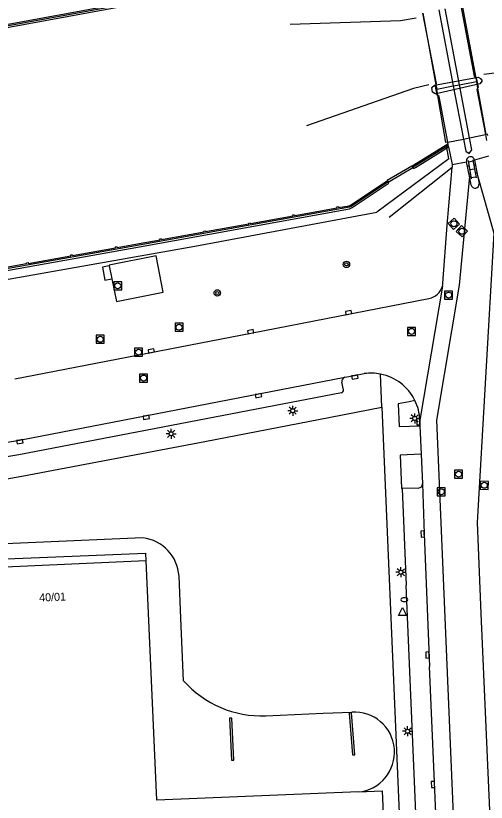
# Model space of a CAD drawing. Extents: x 132999 to 136000, y 398499 to 400501.
# Drawn here: x 133423.1 to 133482, y 398750.4 to 398848.7 of the extents above; entities that cross this region are included whole.
import ezdxf

# ---------------------------------------------------------------- set-up
doc = ezdxf.new("R2010")
doc.units = 0
for name, color, linetype in [('gg-afsc-hekwerk', 7, 'Continuous'), ('gg-afsc-muur', 7, 'Continuous'), ('gg-anno-huisnummerreeks BGT', 7, 'Continuous'), ('gg-bbg-hoofdgebouw', 7, 'Continuous'), ('gg-bbg-luifel en loopbrug', 7, 'Continuous'), ('gg-bbg-onder overbouw', 7, 'Continuous'), ('gg-bbg-pand overbouw', 7, 'Continuous'), ('gg-knt-BGT kruinlijn', 7, 'Continuous'), ('gg-knt-verharding', 7, 'Continuous'), ('gg-knt-verharding niveau 01', 7, 'Continuous'), ('gg-knt-verharding nz', 7, 'Continuous'), ('gg-kwrk-betonelement', 7, 'Continuous'), ('gg-kwrk-geleidewerk', 7, 'Continuous'), ('gt-grn-weggrens', 7, 'Continuous'), ('gt-symb-boom', 7, 'Continuous'), ('gt-symb-brandkraan', 7, 'Continuous'), ('gt-symb-klinker verharding', 7, 'Continuous'), ('gt-symb-kolk', 7, 'Continuous'), ('gt-symb-lichtmast', 7, 'Continuous'), ('gt-symb-rioolschacht', 7, 'Continuous'), ('gt-symb-waterafsluiter', 7, 'Continuous'), ('gx-grn-maaiveld', 7, 'Continuous')]:
    doc.layers.add(name, color=color, linetype=linetype)

# ---------------------------------------------------------------- blocks, each defined once
blk = doc.blocks.new('gt0-RS')
at = {"layer": 'gt-symb-rioolschacht'}
blk.add_lwpolyline([(-0.5, -0.5), (0.5, -0.5), (0.5, 0.5), (-0.5, 0.5)], close=True, dxfattribs=at)
blk.add_circle((0, 0), 0.375, dxfattribs=at)
blk = doc.blocks.new('gt0-KL1')
at = {"layer": 'gt-symb-klinker verharding'}
for p, q in [((-1.15, 0.3), (1.15, 0.3)), ((-1, -0.3), (-1, 0.3)), ((-0.5, 0.3), (-0.5, 0.45)), ((0, -0.3), (0, 0.3)), ((0.5, 0.3), (0.5, 0.45)), ((1, -0.3), (1, 0.3)), ((-1.15, -0.3), (1.15, -0.3)), ((-0.5, -0.45), (-0.5, -0.3)), ((0.5, -0.45), (0.5, -0.3))]:
    blk.add_line(p, q, dxfattribs=at)
blk = doc.blocks.new('gt0-KOLK')
at = {"layer": 'gt-symb-kolk'}
blk.add_lwpolyline([(0, 0), (0.375, 0), (0.375, 0.4), (-0.375, 0.4), (-0.375, 0), (0, 0)], dxfattribs=at)
blk = doc.blocks.new('gt0-BOOM')
at = {"layer": 'gt-symb-boom'}
for radius in [0.4, 0.2]:
    blk.add_circle((0, 0), radius, dxfattribs=at)
blk = doc.blocks.new('gt0-LMAST')
at = {"layer": 'gt-symb-lichtmast'}
for p, q in [((-0.182, 0.173), (-0.447, 0.438)), ((-0.005, 0.246), (-0.005, 0.621)), ((0.172, 0.173), (0.437, 0.438)), ((-0.255, -0.004), (-0.63, -0.004)), ((-0.182, -0.181), (-0.447, -0.446)), ((-0.005, -0.254), (-0.005, -0.629)), ((0.437, -0.446), (0.172, -0.181)), ((0.245, -0.004), (0.62, -0.004))]:
    blk.add_line(p, q, dxfattribs=at)
blk.add_circle((-0.005, -0.004), 0.25, dxfattribs=at)
blk = doc.blocks.new('gt0-WAFSL')
at = {"layer": 'gt-symb-waterafsluiter'}
for p, q in [((-0.5, -0.333), (0, 0.667)), ((0, 0.667), (0.5, -0.333)), ((0.5, -0.333), (-0.5, -0.333))]:
    blk.add_line(p, q, dxfattribs=at)
blk = doc.blocks.new('gt0-BR')
at = {"layer": 'gt-symb-brandkraan'}
for centre, radius, start, end in [((-0.244, 0), 0.206, 107.56694, 252.43307), ((0.599, -2.664), 3, 106.89205, 107.56694), ((0, -0.691), 0.938, 73.10799, 106.89205), ((-0.599, -2.664), 3, 72.43309, 73.10799), ((0.244, 0), 0.206, 287.56695, 72.43309), ((0.599, 2.664), 3, 252.43307, 253.10797), ((0, 0.691), 0.938, 253.10797, 286.89206), ((-0.599, 2.664), 3, 286.89206, 287.56695)]:
    blk.add_arc(centre, radius, start, end, dxfattribs=at)

msp = doc.modelspace()

# ---------------------------------------------------------------- linework, layer by layer
at = {"layer": 'gg-afsc-hekwerk'}
for p, q in [((133476.018, 398849.386), (133477.829, 398839.889)), ((133478.62, 398840.037), (133476.823, 398849.542)), ((133477.829, 398839.889), (133479.095, 398833.253)), ((133479.873, 398833.409), (133478.62, 398840.037)), ((133481.849, 398833.804), (133481.988, 398833.081)), ((133477.253, 398832.286), (133477.142, 398832.862)), ((133469.828, 398823.495), (133477.677, 398829.729)), ((133468.883, 398799.753), (133474.043, 398679.467))]:
    msp.add_line(p, q, dxfattribs=at)
for points in [[(133478.767, 398849.918), (133480.439, 398841.096), (133480.639, 398840.861)], [(133475.665, 398840.028), (133475.725, 398840.213), (133474.043, 398849.004)], [(133480.639, 398840.861), (133480.734, 398840.749), (133480.925, 398839.682), (133480.871, 398839.593)], [(133475.902, 398838.682), (133475.815, 398838.754), (133475.613, 398839.87), (133475.665, 398840.028)], [(133480.871, 398839.593), (133480.777, 398839.437), (133481.849, 398833.804)], [(133477.142, 398832.862), (133476.046, 398838.563), (133475.902, 398838.682)], [(133479.095, 398833.253), (133479.381, 398831.751), (133479.821, 398831.465), (133480.156, 398831.914), (133479.873, 398833.409)], [(133415.609, 398789.703), (133415.609, 398789.722), (133417.98, 398790.069), (133423.912, 398791.103), (133446.77, 398795.458), (133462.485, 398798.488), (133468.883, 398799.753)]]:
    msp.add_lwpolyline(points, dxfattribs=at)
at = {"layer": 'gg-afsc-muur'}
for points in [[(133472.587, 398856.696), (133472.231, 398856.63), (133456.851, 398853.792), (133440.667, 398850.81), (133421.336, 398847.253), (133415.37, 398846.154), (133409.432, 398845.103), (133403.529, 398844.097), (133397.579, 398843.125), (133391.652, 398842.19), (133385.708, 398841.335), (133379.726, 398840.569), (133373.787, 398839.803), (133367.81, 398839.049), (133361.852, 398838.439), (133355.825, 398837.84), (133349.854, 398837.251), (133343.856, 398836.777), (133337.878, 398836.337)], [(133477.129, 398832.399), (133473.007, 398829.849), (133472.837, 398829.744)], [(133469.643, 398827.875), (133469.585, 398827.836), (133465.078, 398824.837), (133464.842, 398824.728)], [(133464.842, 398824.728), (133438.592, 398819.995), (133415.21, 398815.818), (133393.006, 398811.801), (133369.98, 398807.654), (133351.29, 398804.346)], [(133450.387, 398755.638), (133450.164, 398760.867), (133449.872, 398760.858), (133450.095, 398755.63), (133450.387, 398755.638)], [(133465.113, 398761.532), (133464.828, 398761.51), (133465.225, 398756.292), (133465.51, 398756.314), (133465.113, 398761.532)]]:
    msp.add_lwpolyline(points, dxfattribs=at)
at = {"layer": 'gg-bbg-hoofdgebouw'}
for points in [[(133465.972, 398751.653), (133440.764, 398750.615), (133439.456, 398780.533), (133439.39, 398780.53)], [(133465.972, 398751.653), (133468.944, 398751.775), (133472.201, 398676.846)]]:
    msp.add_lwpolyline(points, dxfattribs=at)
at = {"layer": 'gg-bbg-luifel en loopbrug'}
msp.add_line((133439.039, 398783.401), (133415.805, 398782.401), dxfattribs=at)
for points in [[(133444.131, 398765.558), (133443.786, 398773.361), (133443.555, 398778.625)], [(133454.395, 398761.168), (133461.581, 398761.48), (133465.131, 398761.631)]]:
    msp.add_lwpolyline(points, dxfattribs=at)
for centre, radius, start, end in [((133438.449, 398778.32), 5.115, 3.41746, 83.37698), ((133453.852, 398774.093), 12.936, 221.28112, 272.40526), ((133465.479, 398756.636), 5.007, 275.64532, 93.9903)]:
    msp.add_arc(centre, radius, start, end, dxfattribs=at)
at = {"layer": 'gg-bbg-onder overbouw'}
msp.add_line((133439.39, 398780.53), (133415.901, 398779.498), dxfattribs=at)
at = {"layer": 'gg-bbg-pand overbouw'}
msp.add_lwpolyline([(133415.867, 398780.523), (133439.348, 398781.513), (133439.39, 398780.53)], dxfattribs=at)
at = {"layer": 'gg-knt-BGT kruinlijn'}
msp.add_line((133477.271, 398830.759), (133468.28, 398824.1), dxfattribs=at)
msp.add_lwpolyline([(133349.433, 398802.862), (133445.51, 398819.867), (133468.28, 398824.1)], dxfattribs=at)
at = {"layer": 'gg-knt-verharding'}
for p, q in [((133477.271, 398830.759), (133477.034, 398832.134)), ((133480.479, 398830.633), (133480.854, 398828.686)), ((133477.075, 398822.51), (133477.677, 398829.729)), ((133477.707, 398830.09), (133477.677, 398829.729)), ((133479.838, 398828.612), (133479.483, 398830.421)), ((133480.059, 398827.484), (133479.838, 398828.612)), ((133480.854, 398828.686), (133481.044, 398827.701)), ((133476.527, 398815.225), (133477.075, 398822.51)), ((133464.094, 398801.905), (133463.912, 398802.879)), ((133473.643, 398798.135), (133473.669, 398797.419)), ((133473.669, 398797.419), (133473.829, 398793.871)), ((133473.829, 398793.871), (133473.984, 398790.154)), ((133473.501, 398789.639), (133471.451, 398789.572)), ((133471.451, 398789.572), (133471.943, 398777.489)), ((133473.343, 398744.516), (133471.943, 398777.489))]:
    msp.add_line(p, q, dxfattribs=at)
for points in [[(133434.828, 398817.399), (133433.983, 398817.232), (133434.279, 398815.612), (133435.153, 398815.793)], [(133476.468, 398814.878), (133476.505, 398815.05), (133476.527, 398815.225)], [(133423.047, 398803.275), (133452.544, 398808.978), (133474.794, 398813.324)], [(133464.293, 398803.482), (133465.486, 398803.713), (133466.71, 398803.939)], [(133463.844, 398801.547), (133423.552, 398793.788), (133411.281, 398791.735), (133400.408, 398790.097), (133392.18, 398788.941), (133384.422, 398787.939), (133376.657, 398786.994), (133376.446, 398788.78)], [(133473.029, 398800.595), (133472.306, 398800.407), (133470.951, 398800.161), (133471.057, 398797.317), (133473.669, 398797.419)], [(133473.829, 398793.871), (133471.21, 398793.763), (133471.374, 398789.58), (133471.451, 398789.572)]]:
    msp.add_lwpolyline(points, dxfattribs=at)
for centre, radius, start, end in [((133479.981, 398830.527), 0.509, 12.01616, 192.01616), ((133480.546, 398827.619), 0.505, 195.53706, 9.31106), ((133474.425, 398815.4), 2.108, 280.07432, 345.66773), ((133467.542, 398797.882), 6.114, 78.68291, 97.82178), ((133464.421, 398802.979), 0.519, 104.29763, 191.12964), ((133467.544, 398797.872), 6.124, 26.40585, 78.72095), ((133463.802, 398801.843), 0.298, 278.05827, 12.08668), ((133467.793, 398797.982), 5.852, 1.50237, 26.52627), ((133473.473, 398790.15), 0.511, 273.18483, 0.48819)]:
    msp.add_arc(centre, radius, start, end, dxfattribs=at)
at = {"layer": 'gg-knt-verharding niveau 01'}
for p, q in [((133478.93, 398849.95), (133480.639, 398840.861)), ((133474.043, 398849.004), (133475.665, 398840.028)), ((133478.62, 398840.037), (133480.72, 398840.43)), ((133480.639, 398840.861), (133480.72, 398840.43)), ((133480.72, 398840.43), (133480.871, 398839.593)), ((133475.665, 398840.028), (133475.76, 398839.501)), ((133475.76, 398839.501), (133477.829, 398839.889)), ((133475.902, 398838.682), (133475.76, 398839.501)), ((133477.829, 398839.889), (133478.62, 398840.037)), ((133480.871, 398839.593), (133481.917, 398833.818)), ((133476.916, 398832.817), (133475.902, 398838.682)), ((133479.873, 398833.409), (133481.849, 398833.804)), ((133481.849, 398833.804), (133481.917, 398833.818)), ((133477.096, 398832.853), (133476.916, 398832.817)), ((133477.142, 398832.862), (133477.096, 398832.853)), ((133477.142, 398832.862), (133479.095, 398833.253)), ((133479.095, 398833.253), (133479.873, 398833.409))]:
    msp.add_line(p, q, dxfattribs=at)
at = {"layer": 'gg-knt-verharding nz'}
for p, q in [((133476.468, 398814.878), (133473.643, 398798.135)), ((133475.862, 398744.188), (133474.863, 398767.351))]:
    msp.add_line(p, q, dxfattribs=at)
for points in [[(133479.838, 398828.612), (133478.576, 398814.993), (133475.742, 398798.139), (133479.596, 398706.39)], [(133480.854, 398828.686), (133482.877, 398821.491), (133480.81, 398785.33), (133481.292, 398773.949)], [(133376.446, 398788.78), (133386.883, 398790.046), (133393.094, 398790.882), (133407.471, 398792.974), (133415.547, 398794.27), (133423.613, 398795.63), (133464.293, 398803.482)], [(133473.984, 398790.154), (133474.207, 398783.9), (133474.863, 398767.351)], [(133481.292, 398773.949), (133484.216, 398706.711), (133485.58, 398674.477)]]:
    msp.add_lwpolyline(points, dxfattribs=at)
at = {"layer": 'gg-kwrk-betonelement'}
msp.add_line((133434.828, 398817.399), (133435.153, 398815.793), dxfattribs=at)
msp.add_lwpolyline([(133435.153, 398815.793), (133435.722, 398812.962), (133441.581, 398814.108), (133440.688, 398818.652), (133434.817, 398817.506), (133434.828, 398817.399)], dxfattribs=at)
at = {"layer": 'gg-kwrk-geleidewerk'}
for points in [[(133473.184, 398848.366), (133471.238, 398848.046), (133457.43, 398847.577)], [(133481.667, 398841.364), (133484.326, 398841.71), (133497.434, 398841.736)], [(133474.769, 398840.036), (133472.844, 398839.589), (133459.504, 398834.891)]]:
    msp.add_lwpolyline(points, dxfattribs=at)
at = {"layer": 'gt-grn-weggrens'}
for p, q in [((133482.246, 398831.116), (133480.479, 398830.633)), ((133477.707, 398830.09), (133479.483, 398830.421)), ((133468.883, 398799.753), (133468.742, 398803.877))]:
    msp.add_line(p, q, dxfattribs=at)
at = {"layer": 'gx-grn-maaiveld'}
for p, q in [((133477.096, 398832.853), (133477.143, 398832.614)), ((133477.143, 398832.614), (133477.2, 398832.237)), ((133477.253, 398832.286), (133477.707, 398830.09)), ((133469.701, 398827.882), (133472.772, 398829.71)), ((133472.685, 398829.856), (133472.772, 398829.71)), ((133469.598, 398828.055), (133469.701, 398827.882))]:
    msp.add_line(p, q, dxfattribs=at)
for points in [[(133337.863, 398836.536), (133343.841, 398836.976), (133349.836, 398837.45), (133355.805, 398838.039), (133361.832, 398838.638), (133367.787, 398839.248), (133373.762, 398840.001), (133379.701, 398840.767), (133385.681, 398841.533), (133391.622, 398842.388), (133397.547, 398843.322), (133403.496, 398844.294), (133409.398, 398845.3), (133415.334, 398846.351), (133421.3, 398847.45), (133440.631, 398851.007), (133456.815, 398853.989), (133472.195, 398856.827), (133472.604, 398856.903)], [(133337.892, 398836.137), (133343.871, 398836.577), (133349.871, 398837.052), (133355.844, 398837.641), (133361.872, 398838.24), (133367.832, 398838.851), (133373.813, 398839.604), (133379.752, 398840.37), (133385.735, 398841.137), (133391.682, 398841.993), (133397.61, 398842.927), (133403.562, 398843.9), (133409.467, 398844.906), (133415.405, 398845.957), (133421.373, 398847.057), (133440.703, 398850.614), (133456.888, 398853.596), (133472.268, 398856.434), (133472.669, 398856.508)], [(133475.478, 398839.967), (133480.956, 398840.971), (133481.247, 398840.835), (133481.437, 398840.543), (133481.133, 398840.136), (133475.683, 398838.9), (133475.567, 398838.898), (133475.214, 398839.122), (133475.141, 398839.692), (133475.478, 398839.967)], [(133482.139, 398833.714), (133482.113, 398833.858), (133481.917, 398833.818)], [(133477.143, 398832.614), (133472.915, 398829.998), (133472.685, 398829.856)], [(133472.772, 398829.71), (133472.866, 398829.558), (133473.099, 398829.7), (133476.511, 398831.81), (133477.034, 398832.134)], [(133477.2, 398832.237), (133477.089, 398832.168), (133477.034, 398832.134)], [(133477.2, 398832.237), (133477.252, 398832.286), (133477.253, 398832.286)], [(133469.598, 398828.055), (133469.573, 398828.097), (133472.644, 398829.925), (133472.685, 398829.856)], [(133419.165, 398816.728), (133424.51, 398817.683), (133424.491, 398817.795), (133424.688, 398817.829), (133424.707, 398817.718), (133430.05, 398818.672), (133430.035, 398818.763), (133430.232, 398818.797), (133430.247, 398818.707), (133435.631, 398819.669), (133435.615, 398819.761), (133435.812, 398819.795), (133435.827, 398819.704), (133438.556, 398820.192), (133441.18, 398820.665), (133441.162, 398820.767), (133441.359, 398820.801), (133441.376, 398820.7), (133446.678, 398821.656), (133446.663, 398821.745), (133446.86, 398821.779), (133446.875, 398821.692), (133452.281, 398822.666), (133452.268, 398822.745), (133452.465, 398822.779), (133452.478, 398822.702), (133457.814, 398823.664), (133457.798, 398823.76), (133457.995, 398823.794), (133458.011, 398823.699), (133463.308, 398824.654), (133463.286, 398824.782), (133463.483, 398824.816), (133463.505, 398824.69), (133464.807, 398824.925), (133464.81, 398824.906), (133464.981, 398824.983), (133469.598, 398828.055)], [(133464.878, 398824.531), (133464.875, 398824.55), (133465.175, 398824.692), (133469.682, 398827.691), (133469.776, 398827.753), (133469.701, 398827.882)], [(133337.611, 398806.534), (133349.847, 398804.341), (133351.086, 398804.187), (133351.324, 398804.157), (133351.325, 398804.149), (133370.015, 398807.457), (133393.041, 398811.604), (133415.245, 398815.621), (133438.627, 398819.798), (133464.878, 398824.531)]]:
    msp.add_lwpolyline(points, dxfattribs=at)

# ---------------------------------------------------------------- block references
at = {"layer": 'gt-symb-boom'}
for p in [(133464.477, 398817.588), (133448.335, 398814.02)]:
    msp.add_blockref('gt0-BOOM', p, dxfattribs=at)
at = {"layer": 'gt-symb-brandkraan'}
msp.add_blockref('gt0-BR', (133471.706, 398775.686), dxfattribs=at)
at = {"layer": 'gt-symb-klinker verharding', "rotation": -80.5565250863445}
msp.add_blockref('gt0-KL1', (133480.185, 398829.48), dxfattribs=at)
at = {"layer": 'gt-symb-kolk'}
for p, rotation in [((133464.784, 398811.368), 10.952273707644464), ((133452.544, 398808.978), 10.952273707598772), ((133440.123, 398806.579), 10.952273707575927), ((133465.486, 398803.713), -169.52409816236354), ((133453.446, 398801.387), -169.10581701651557), ((133439.421, 398798.669), -169.10581701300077), ((133473.649, 398797.908), 92.25190845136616), ((133423.613, 398795.63), -169.5106101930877), ((133474.207, 398783.9), 92.25190845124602), ((133474.801, 398768.78), 92.38930346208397), ((133475.495, 398752.602), 92.45414686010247)]:
    msp.add_blockref('gt0-KOLK', p, dxfattribs=dict(at, rotation=rotation))
at = {"layer": 'gt-symb-lichtmast'}
for p in [(133457.776, 398799.304), (133473.021, 398798.349), (133442.575, 398796.418), (133471.282, 398779.119), (133472.119, 398759.236)]:
    msp.add_blockref('gt0-LMAST', p, dxfattribs=at)
at = {"layer": 'gt-symb-rioolschacht'}
for p, rotation in [((133477.916, 398822.662), -138.32364227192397), ((133478.907, 398821.722), -132.40480040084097), ((133481.704, 398789.977), 89.25519682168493)]:
    msp.add_blockref('gt0-RS', p, dxfattribs=dict(at, rotation=rotation))
for p in [(133435.887, 398814.908), (133477.251, 398813.747), (133443.562, 398809.735), (133472.615, 398809.21), (133433.705, 398808.228), (133438.498, 398806.614), (133439.131, 398803.388), (133478.501, 398791.367), (133476.332, 398789.169)]:
    msp.add_blockref('gt0-RS', p, dxfattribs=at)
at = {"layer": 'gt-symb-waterafsluiter'}
msp.add_blockref('gt0-WAFSL', (133471.481, 398774.028), dxfattribs=at)

# ---------------------------------------------------------------- texts
at = {"layer": 'gg-anno-huisnummerreeks BGT'}
msp.add_text('40/01', height=1, rotation=2.5, dxfattribs=at).set_placement((133426.097, 398775.442))

doc.saveas('drawing.dxf')
